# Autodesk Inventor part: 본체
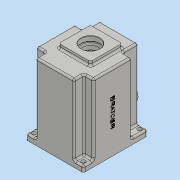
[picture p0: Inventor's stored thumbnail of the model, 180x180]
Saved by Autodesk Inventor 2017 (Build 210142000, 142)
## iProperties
Part Number: 본체
Material: 일반
Document SubType Name: Modeling
Designer: MRC
Density: 1 g/cm^3
Appearance: 기본값
Author: MRC
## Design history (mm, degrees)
sketch "스케치1"
  geometry: L1 (-49, -55)-(49, -55); L2 (49, -55)-(49, 55); L3 (49, 55)-(-49, 55); L4 (-49, 55)-(-49, -55); 3 further points
  constraints: 8 end point, 2 midpoint, 2 parallel, 1 horizontal, 1 horizontal alignment, 1 perpendicular, 1 vertical alignment
  dimensions: "d11" = 98 distance of L2.end L3.end; "d12" = 110 distance of L3.end L1.start
extrude "돌출1" new body sketch "스케치1" distance "d13" = 130; taper "d14" = 0 deg
sketch "스케치2"
  geometry: L1 (33, 28)-(49, 28); L2 (49, 28)-(49, 55); L3 (49, 55)-(33, 55); L4 (33, 55)-(33, 28); L5 (-49, 28)-(-33, 28); L6 (-33, 28)-(-33, 55); L7 (-33, 55)-(-49, 55); L8 (-49, 55)-(-49, 28); 3 further points
  constraints: 16 end point, 4 parallel, 2 coincident, 2 horizontal, 2 perpendicular
  dimensions: "d15" = 16 distance of L2.end L3.end; "d16" = 27 distance of L3.end L1.start; "d17" = 16 distance of L6.end L7.end; "d18" = 27 distance of L7.end L5.start
extrude "돌출2" cut sketch "스케치2" distance "d19" = 120; taper "d20" = 0 deg
sketch "스케치3"
  geometry: L1 (33, -55)-(49, -55); L2 (49, -55)-(49, -38); L3 (49, -38)-(33, -38); L4 (33, -38)-(33, -55); L5 (-49, -55)-(-33, -55); L6 (-33, -55)-(-33, -38); L7 (-33, -38)-(-49, -38); L8 (-49, -38)-(-49, -55); 3 further points
  constraints: 16 end point, 4 parallel, 2 coincident, 2 horizontal, 2 perpendicular
  dimensions: "d21" = 17 distance of L1.end L2.end; "d22" = 17 distance of L5.end L6.end; "d23" = 16 distance of L2.end L3.end; "d24" = 16 distance of L6.end L7.end
extrude "돌출3" cut sketch "스케치3" distance "d25" = 120; taper "d26" = 0 deg
fillet "모깎기1" dims "d27" = 3
sketch "스케치5"
  geometry: L1 (-20, 45)-(20, 45); L2 (23, 42)-(23, 33.249); L3 (-23, 33.249)-(-23, 42); L4 (46, -55)-(-46, -55) reference; L5 (-26, 42)-(-26, 33.249); L6 (26, 33.249)-(26, 42); L7 (20, 48)-(-20, 48); A1 r 42 centre (0, -5) between (-25.375, 28.468) and (25.375, 28.468); A2 r 6 centre (-29, 33.249) between (-25.375, 28.468) and (-23, 33.249); A3 r 6 centre (29, 33.249) between (23, 33.249) and (25.375, 28.468); A4 r 3 centre (-20, 42) between (-20, 45) and (-23, 42); A5 r 3 centre (20, 42) between (23, 42) and (20, 45); A6 r 3 centre (-29, 33.249) between (-27.187, 30.859) and (-26, 33.249); A7 r 45 centre (0, -5) between (-27.187, 30.859) and (27.187, 30.859); A8 r 3 centre (29, 33.249) between (26, 33.249) and (27.187, 30.859); A9 r 6 centre (20, 42) between (26, 42) and (20, 48); A10 r 6 centre (-20, 42) between (-20, 48) and (-26, 42); 6 further points
  constraints: 22 point on circle, 12 end point, 10 centre point, 8 tangent, 6 point on line, 2 equal radius, 2 parallel, 2 perpendicular, 2 vertical alignment, 1 horizontal, 1 midpoint, 7 other
  dimensions: "d39" = 46 distance of point (-23, 45) point (23, 45); "d40" = 84 diameter of A1; "d41" = 50 distance from line of L4 A1.centre; "d42" = 50 distance from line of L1 A1.centre; "d43" = 6 radius of A2 (derived); "d44" = 3 radius of A4 (derived); "d47" = 3 distance between parallel lines of L3 L5
extrude "돌출6" cut sketch "스케치5" distance "d45" = 121; taper "d46" = 0 deg
extrude "돌출7" cut sketch "스케치5" distance "d48" = 9; taper "d49" = 0 deg
sketch "스케치6"
  geometry: C1 r 21 at (0, 6); C2 r 15 at (0, -25); A1 r 42 centre (0, -5) between (-25.375, 28.468) and (25.375, 28.468) reference; 1 further point
  constraints: 2 centre point, 2 vertical alignment
  dimensions: "d50" = 11 distance of C1.centre A1.centre; "d51" = 20 distance of C2.centre A1.centre; "d52" = 42 diameter of C1; "d53" = 30 diameter of C2
extrude "돌출8" join sketch "스케치6" distance "d54" = 7; taper "d55" = 0 deg
fillet "모깎기2" dims "d56" = 3
sketch "스케치9"
  geometry: L1 (-24, -21)-(24, -21); L2 (27, -18)-(27, 30); L3 (24, 33)-(-24, 33); L4 (-27, 30)-(-27, -18); A1 r 21 centre (0, 6) between (12.163, -11.119) and (-12.163, -11.119) reference; A2 r 3 centre (-24, 30) between (-24, 33) and (-27, 30); A3 r 3 centre (24, 30) between (27, 30) and (24, 33); A4 r 3 centre (24, -18) between (24, -21) and (27, -18); A5 r 3 centre (-24, -18) between (-27, -18) and (-24, -21); 6 further points
  constraints: 8 end point, 8 point on circle, 8 tangent, 6 point on line, 4 centre point, 3 equal radius, 2 midpoint, 2 parallel, 1 horizontal, 1 horizontal alignment, 1 perpendicular, 1 vertical alignment
  dimensions: "d63" = 54 distance of point (27, 33) point (-27, 33); "d64" = 54 distance of point (-27, 33) point (-27, -21); "d65" = 3 radius of A2 (derived)
extrude "돌출10" join sketch "스케치9" distance "d66" = 7; taper "d67" = 0 deg
fillet "모깎기4" dims "d68" = 3
sketch "스케치10"
  geometry: C1 r 16 at (0, 6); A1 r 21 centre (0, 6) between (12.163, -11.119) and (-12.163, -11.119) reference; 1 further point
  constraints: 1 centre point, 1 coincident
  dimensions: "d69" = 32 diameter of C1
extrude "돌출11" cut sketch "스케치10" distance "d70" = 8.3; taper "d71" = 0 deg
sketch "스케치11"
  geometry: C1 r 17.5 at (0, 6); A1 r 21 centre (0, 6) between (12.163, -11.119) and (-12.163, -11.119) reference; 1 further point
  constraints: 1 centre point, 1 coincident
  dimensions: "d72" = 35 diameter of C1
extrude "돌출12" cut sketch "스케치11" distance "d73" = 10; taper "d74" = 0 deg
sketch "스케치12"
  geometry: C1 r 17.5 at (0, 0) reference; C2 r 14 at (0, 0); 1 further point
  constraints: 1 centre point, 1 coincident
  dimensions: "d75" = 28 diameter of C2
extrude "돌출13" cut sketch "스케치12" stored distance "d76" = 10; taper "d77" = 0 deg
sketch "스케치13"
  geometry: L1 (22.462, 137)-(22, 136.2); L2 (22, 136.2)-(22, 137); L3 (22, 137)-(22.462, 137); L4 (22, 137)-(22, 128.7) reference; L5 (-10, 137)-(22, 137) reference; L6 (6, 137)-(6, 114); L7 (23.5, 114)-(-11.5, 114) reference; 1 further point
  constraints: 8 end point, 2 midpoint, 1 perpendicular, 1 vertical
  dimensions: "d78" = 30 deg angle of L2 L1; "d79" = 0.8 distance of L2.end L1.end
revolve "회전1" sketch "스케치13" stored, may be unused: angle "d80" = 90 deg
fillet "모깎기5" dims "d81" = 0.3
hole "구멍1" diameter "d84" = 19; stored, may be unused: countersink angle "d88" = 90 deg, drill point angle "d90" = 0 deg; dims "d82" = 10, "d83" = 10, "d85" = 6, "d86" = 22, "d87" = 7, "d89" = 10
fillet "모깎기6" dims "d91" = 3
fillet "모깎기7" dims "d92" = 0.3
fillet "모깎기8" dims "d93" = 3
sketch "스케치15"
  geometry: L1 (92, 0)-(0, 0) reference; C1 r 22.5 at (46, -40); 2 further points
  constraints: 1 centre point, 1 midpoint, 1 vertical alignment
  dimensions: "d94" = 45 diameter of C1; "d95" = 40 distance of point (46, 0) C1.centre
extrude "돌출14" join sketch "스케치15" distance "d96" = 10; taper "d97" = 0 deg
sketch "스케치16"
  geometry: L1 (92, 0)-(0, 0) reference; C1 r 15 at (46, -89); 2 further points
  constraints: 1 centre point, 1 midpoint, 1 vertical alignment
  dimensions: "d98" = 30 diameter of C1; "d99" = 89 distance of C1.centre point (46, 0)
extrude "돌출15" join sketch "스케치16" distance "d100" = 5; taper "d101" = 0 deg
sketch "스케치17"
  geometry: C1 r 15 at (20, -32) reference; 2 further points
  constraints: 1 coincident
hole "구멍2" sketch "스케치17" at (20, -32) diameter "d102" = 20; stored, may be unused: countersink angle "d106" = 90 deg, drill point angle "d108" = 0 deg; dims "d103" = 6, "d104" = 30, "d105" = 5, "d107" = 10
hole "구멍3" diameter "d111" = 33.376; stored, may be unused: countersink angle "d115" = 90 deg, drill point angle "d117" = 0 deg; dims "d109" = 10, "d110" = 10, "d112" = 70, "d113" = 30, "d114" = 5, "d116" = 77.3
fillet "모깎기9" dims "d118" = 3
chamfer "모따기1" distance "d119" = 1; stored, may be unused: second distance "d120" = 2, angle "d121" = 45 deg
fillet "모깎기10" dims "d122" = 3
sketch "스케치18"
  geometry: L1 (-46, 55)-(46, 55) reference; L2 (-49, -52)-(-49, 52) reference; L3 (0, 0)-(0, 8.024); L4 (0, 0)-(-4.182, 0); C1 r 3.5 at (-42, 48); C2 r 3.5 at (42, 48); C3 r 3.5 at (42, -48); C4 r 3.5 at (-42, -48)
  constraints: 4 centre point, 4 end point, 3 symmetric about line, 1 horizontal, 1 vertical, 3 other
  dimensions: "d123" = 7 diameter of C1; "d124" = 7 distance from line of L1 C1.centre; "d125" = 7 distance from line of L2 C1.centre
extrude "돌출16" cut sketch "스케치18" distance "d126" = 10; taper "d127" = 0 deg
sketch "스케치19"
  geometry: L1 (35.777, -1)-(41.809, -1); L2 (35.777, -9)-(41.809, -9); A1 r 42 centre (0, -5) between (-25.375, 28.468) and (25.375, 28.468) reference; A2 r 36 centre (0, -5) between (36, -5) and (35.777, -9); A3 r 4 centre (36, -5) between (36, -1) and (36, -9); 1 further point
  constraints: 7 point on circle, 4 end point, 2 centre point, 2 horizontal, 2 point on line, 2 tangent, 1 coincident, 1 horizontal alignment
  dimensions: "d128" = 72 diameter of A2; "d129" = 8 diameter of A3
extrude "돌출17" join sketch "스케치19" stored distance "d130" = 10; taper "d131" = 0 deg
fillet "모깎기11" dims "d132" = 3
hole "구멍4" diameter "d135" = 3.242; stored, may be unused: countersink angle "d139" = 90 deg, drill point angle "d141" = 118 deg; dims "d136" = 7, "d137" = 30, "d138" = 5, "d140" = 9, "d142" = 10, "d143" = 10
sketch "스케치20"
  geometry: L1 (-130, 104)-(-130, 83) reference; L2 (-13, 80)-(-127, 80) reference; 2 further points
  constraints: 1 other
  dimensions: "d144" = 65 distance from line of L1 point (-65, 47); "d145" = 33 distance from line of point (-65, 47) L2
feature "엠보싱1" sketch "스케치20" dims "d146" = 0.5, "d147" = 0
node "솔리드1"
mirror "미러1"
node "작업 평면1"
